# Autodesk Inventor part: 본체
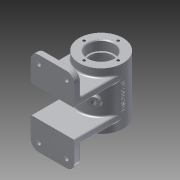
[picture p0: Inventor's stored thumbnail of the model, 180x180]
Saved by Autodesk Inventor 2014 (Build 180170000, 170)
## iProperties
Created: 2017-02
Part Number: 본체
Material: 알루미늄 6061
Document SubType Name: Modeling
Designer: 601-
Mass: 356.065 g
Surface Area: 422.773 cm^2
Volume: 131.389 cm^3
Density: 2.71 g/cm^3
Appearance: 알루미늄 - 평지
Author: 601-
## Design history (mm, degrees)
sketch "스케치4"
  geometry: L1 (0, 0)-(0, 60); C1 r 27 at (0, 60)
  constraints: 2 end point, 1 centre point, 1 coincident, 1 vertical
  dimensions: "d4" = 60 distance of L1.start L1.end; "d5" = 54 diameter of C1
extrude "돌출2" new body sketch "스케치4" stored distance "d6" = 70; taper "d7" = 0 deg
sketch "스케치5"
  geometry: L1 (-27, -52)-(27, -52); L2 (27, -52)-(27, 52); L3 (27, 52)-(-27, 52); L4 (-27, 52)-(-27, -52); L5 (-27, -52)-(27, 52); L6 (27, -52)-(-27, 52); L7 (0, 0)-(0, -17); L8 (0, -17)-(27, -17); L9 (0, -17)-(-27, -17); L10 (0, 0)-(0, 17); L11 (0, 17)-(27, 17); L12 (0, 17)-(-27, 17)
  constraints: 24 end point, 6 perpendicular, 4 point on line, 3 parallel, 2 midpoint, 1 horizontal
  dimensions: "d8" = 54 distance of L3.end L2.end; "d9" = 104 distance of L2.end L1.end; "d10" = 17 distance of L7.start L7.end; "d11" = 17 distance of L7.start L10.end
extrude "돌출3" join sketch "스케치5" distance "d12" = 8; taper "d13" = 0 deg
sketch "스케치7"
  geometry: L1 (27, -52)-(27, -17) reference; L2 (-27, -17)-(27, -17); L3 (27, -17)-(27, -25); L4 (27, -25)-(-27, -25); L5 (-27, -25)-(-27, -17); L6 (-27, 17)-(27, 17); L7 (27, 17)-(27, 25); L8 (27, 25)-(-27, 25); L9 (-27, 25)-(-27, 17); 1 further point
  constraints: 16 end point, 4 parallel, 2 horizontal, 2 perpendicular, 1 point on line
  dimensions: "d22" = 8 distance of L2.end L3.end; "d23" = 8 distance of L7.end L6.end; "d24" = 54 distance between parallel lines of L9 L7
extrude "돌출4" join sketch "스케치7" stored distance "d25" = 54; taper "d26" = 0 deg
sketch "스케치8"
  geometry: L1 (87, 35)-(33, 35) reference; L2 (60, 35)-(60, -35); L3 (33, -35)-(87, -35) reference; L4 (60, 35)-(76, 35); L5 (76, 35)-(76, 23); L6 (76, 23)-(74, 23); L7 (74, 23)-(74, 20); L8 (60, -35)-(76, -35); L9 (76, -35)-(76, -23); L10 (76, -23)-(74, -23); L11 (74, -23)-(74, -20); L12 (74, -20)-(82, -20); L13 (82, -20)-(82, 20); L14 (82, 20)-(74, 20); 1 further point
  constraints: 24 end point, 6 perpendicular, 2 midpoint, 2 parallel, 2 point on line
  dimensions: "d27" = 16 distance of L2.start L4.end; "d28" = 12 distance of L4.end L5.end; "d29" = 2 distance of L5.end L6.end; "d30" = 3 distance of L6.end L7.end; "d31" = 16 distance of L2.end L8.end; "d32" = 12 distance of L8.end L9.end; "d33" = 2 distance of L9.end L10.end; "d34" = 3 distance of L10.end L11.end; "d35" = 8 distance of L11.end L12.end; "d36" = 40 distance of L12.end L13.end
revolve "회전1" sketch "스케치8" stored, may be unused: angle "d37" = 90 deg
sketch "스케치9"
  geometry: L1 (44, 35)-(76, 35) reference; L2 (60, 35)-(60, 10); L3 (60, 10)-(87, 10); L4 (87, 10)-(92, 10); L5 (92, 10)-(92, 15); L6 (92, 15)-(82.5, 15); L7 (82.5, 15)-(82.5, 10); L8 (92, 10)-(82.5, 10); 1 further point
  constraints: 14 end point, 4 perpendicular, 1 collinear, 1 midpoint, 1 point on line
  dimensions: "d39" = 25 distance of L2.start L2.end; "d40" = 27 distance of L2.end L3.end; "d41" = 5 distance of L3.end L4.end; "d42" = 5 distance of L4.end L5.end; "d43" = 9.5 distance of L5.end L6.end; "d44" = 5 distance of L6.end L7.end
revolve "회전2" sketch "스케치9" stored, may be unused: angle "d45" = 90 deg
sketch "스케치10"
  geometry: L1 (0, 60)-(16.339, 34.84); L2 (0, 60)-(30, 60); L3 (16.339, 34.84)-(11.307, 31.572); L4 (11.307, 31.572)-(7.495, 37.443); L5 (7.495, 37.443)-(12.527, 40.711); L6 (12.527, 40.711)-(16.339, 34.84); C1 r 14 at (0, 60) reference; 1 further point
  constraints: 12 end point, 2 perpendicular, 1 collinear, 1 equal length, 1 horizontal, 1 parallel, 1 point on line
  dimensions: "d46" = 30 distance of L1.start L1.end; "d47" = 57 deg angle of L1 L2; "d48" = 6 distance of L1.end L3.end; "d49" = 7 distance of L3.end L4.end
revolve "회전3" sketch "스케치10" stored, may be unused: angle "d50" = 90 deg
sketch "스케치12" dims "d53" = 9, "d55" = 9, "d56" = 9, "d57" = 9
  geometry: L1 (17, 42)-(-17, 42); L2 (-17, 42)-(-17, -42); L3 (-17, -42)-(17, -42); L4 (17, -42)-(17, 42); L5 (17, 42)-(-17, -42); L6 (-17, 42)-(17, -42); L7 (-12.5, 39.402)-(-17, 36.804); L8 (-17, 36.804)-(-21.5, 39.402); L9 (-21.5, 39.402)-(-21.5, 44.598); L10 (-21.5, 44.598)-(-17, 47.196); L11 (-17, 47.196)-(-12.5, 44.598); L12 (-12.5, 44.598)-(-12.5, 39.402); L13 (12.5, 44.598)-(17, 47.196); L14 (17, 47.196)-(21.5, 44.598); L15 (21.5, 44.598)-(21.5, 39.402); L16 (21.5, 39.402)-(17, 36.804); L17 (17, 36.804)-(12.5, 39.402); L18 (12.5, 39.402)-(12.5, 44.598); L19 (12.5, -39.402)-(17, -36.804); L20 (17, -36.804)-(21.5, -39.402); L21 (21.5, -39.402)-(21.5, -44.598); L22 (21.5, -44.598)-(17, -47.196); L23 (17, -47.196)-(12.5, -44.598); L24 (12.5, -44.598)-(12.5, -39.402); L25 (-12.5, -44.598)-(-17, -47.196); L26 (-17, -47.196)-(-21.5, -44.598); L27 (-21.5, -44.598)-(-21.5, -39.402); L28 (-21.5, -39.402)-(-17, -36.804); L29 (-17, -36.804)-(-12.5, -39.402); L30 (-12.5, -39.402)-(-12.5, -44.598); 13 further points
  constraints: 60 end point, 8 coincident, 6 midpoint, 4 horizontal alignment, 4 point on line, 2 parallel, 1 horizontal, 1 perpendicular, 60 other
  dimensions: "d51" = 34 distance of L3.end L2.end; "d52" = 84 distance of L2.end L1.end
extrude "돌출5" cut sketch "스케치12" distance "d58" = 3; taper "d59" = 0 deg
sketch "스케치14"
  geometry: L1 (-17, 42)-(17, 42); L2 (17, 42)-(17, -42); L3 (17, -42)-(-17, -42); L4 (-17, -42)-(-17, 42); L5 (-17, 42)-(17, -42); L6 (17, 42)-(-17, -42); 1 further point
  constraints: 12 end point, 2 midpoint, 2 parallel, 1 horizontal, 1 perpendicular
  dimensions: "d60" = 34 distance of L2.end L3.end; "d61" = 84 distance of L1.end L2.end
hole "구멍1" sketch "스케치14" at (-17, -42), (17, -42), (17, 42), (-17, 42) diameter "d62" = 5; stored, may be unused: countersink angle "d66" = 90 deg, drill point angle "d68" = 118 deg; dims "d63" = 6, "d64" = 4, "d65" = 2, "d67" = 8
hole "구멍2" diameter "d71" = 5.188; stored, may be unused: countersink angle "d75" = 90 deg, drill point angle "d77" = 118 deg; dims "d69" = 10, "d70" = 10, "d72" = 20, "d73" = 4, "d74" = 2, "d76" = 20
hole "구멍3" diameter "d80" = 5.188; stored, may be unused: countersink angle "d84" = 90 deg, drill point angle "d86" = 118 deg; dims "d78" = 10, "d79" = 10, "d81" = 20, "d82" = 4, "d83" = 2, "d85" = 20
node "작업 평면1"
sketch "스케치15"
  geometry: L1 (27, 35)-(-27, 35) reference; L2 (27, -35)-(27, 35) reference; L3 (27, 35)-(27, 0); L4 (27, 0)-(0, 0); 2 further points
  constraints: 4 end point, 1 coincident, 1 midpoint, 1 perpendicular, 1 other
  dimensions: "d87" = 35 distance of L2.end L3.end; "d88" = 27 distance of L3.end L4.end
feature "엠보싱1" sketch "스케치15" dims "d5" = 54, "d89" = 0.5, "d90" = 0
fillet "모깎기1" dims "d91" = 10
fillet "모깎기2" dims "d92" = 0.3
fillet "모깎기3" dims "d93" = 3
sketch "스케치16"
  geometry: L1 (0, 0)-(0, 21); C1 r 27 at (0, 0) reference; 1 further point
  constraints: 2 end point, 1 vertical
  dimensions: "d94" = 21 distance of L1.start L1.end
hole "구멍4" sketch "스케치16" at (0, 21) diameter "d95" = 3.242; stored, may be unused: countersink angle "d99" = 90 deg, drill point angle "d101" = 118 deg; dims "d96" = 8, "d97" = 4, "d98" = 2, "d100" = 10
sketch "스케치17"
  geometry: L1 (0, 0)-(0, 21); C1 r 27 at (0, 0) reference; 1 further point
  constraints: 2 end point, 1 vertical
  dimensions: "d106" = 21 distance of L1.start L1.end
hole "구멍5" sketch "스케치17" at (0, 21) diameter "d107" = 3.242; stored, may be unused: countersink angle "d111" = 90 deg, drill point angle "d113" = 118 deg; dims "d108" = 8, "d109" = 4, "d110" = 2, "d112" = 10
chamfer "모따기1" distance "d117" = 1; stored, may be unused: second distance "d118" = 2, angle "d119" = 45 deg
chamfer "모따기2" distance "d120" = 1; stored, may be unused: second distance "d121" = 2, angle "d122" = 45 deg
fillet "모깎기4" dims "d123" = 2
fillet "모깎기5" dims "d124" = 2
fillet "모깎기6" dims "d125" = 2
fillet "모깎기7" dims "d126" = 2
node "솔리드2"
pattern_circular "원형 패턴1" dims angle "d103" = 360 deg
pattern_circular "원형 패턴2" dims angle "d115" = 360 deg
